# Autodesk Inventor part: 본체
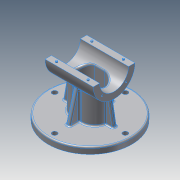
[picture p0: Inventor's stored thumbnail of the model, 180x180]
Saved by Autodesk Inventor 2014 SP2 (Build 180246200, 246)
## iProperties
Created: 2015-12
Part Number: 본체
Material: 알루미늄 6061
Document SubType Name: Modeling
Designer: mduedu
Density: 2.71 g/cm^3
Appearance: 알루미늄 - 평지
Mass: 616.11 g
Surface Area: 573.393 cm^2
Volume: 227.347 cm^3
Author: mduedu
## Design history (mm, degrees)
sketch "스케치1"
  geometry: C1 r 65 at (0, 0); 1 further point
  constraints: 1 centre point, 1 coincident
  dimensions: "d124" = 130 diameter of C1
extrude "돌출1" new body sketch "스케치1" distance "d3" = 10; taper "d4" = 0 deg
sketch "스케치2"
  geometry: C1 r 32.5 at (80, 0); 1 further point
  constraints: 1 centre point, 1 horizontal alignment
  dimensions: "d5" = 65 diameter of C1; "d125" = 80 distance of C1.centre point (0, 0)
extrude "돌출2" join sketch "스케치2" stored distance "d7" = 75; taper "d8" = 0 deg
sketch "스케치3"
  geometry: L1 (-27.5, -20)-(27.5, -20); L2 (27.5, -20)-(27.5, 20); L3 (27.5, 20)-(-27.5, 20); L4 (-27.5, 20)-(-27.5, -20); L5 (-27.5, -20)-(27.5, 20); L6 (27.5, -20)-(-27.5, 20); 1 further point
  constraints: 12 end point, 2 midpoint, 2 parallel, 1 horizontal, 1 perpendicular
  dimensions: "d9" = 55 distance of L2.end L3.end; "d11" = 40 distance of L1.end L2.end
extrude "돌출3" new body sketch "스케치3" stored distance "d12" = 75; taper "d13" = 0 deg
fillet "모깎기1"
fillet "모깎기2"
feature "결합1"
  node "솔리드2"
sketch "스케치4"
  geometry: L1 (-37.5, 47.5)-(37.5, 47.5) reference; L2 (32.5, 47.5)-(39.112, 10); L3 (37.5, 47.5)-(37.5, 112.5) reference; L4 (65, 10)-(-65, 10) reference; 1 further point
  constraints: 2 end point, 2 point on line
  dimensions: "d15" = 5 distance from line of L2.start L3; "d126" = 80 deg angle of L2 L1
sketch "스케치5"
  geometry: L1 (10, 35)-(56.569, 22.522); L2 (10, -65)-(10, 65) reference; L3 (10, 20)-(54.383, 20) reference; A1 r 32.5 centre (80, 0) between (56.569, 22.522) and (54.383, 20) reference; 1 further point
  constraints: 2 end point, 1 point on circle, 1 point on line
  dimensions: "d127" = 75 deg angle of L1 L2; "d128" = 15 distance of L1.start L3.start
feature "리브1" dims "d19" = 1, "d20" = 6, "d21" = 0, "d22" = 0, "d23" = 1, "d24" = 1
feature "리브2" dims "d25" = 1, "d26" = 6, "d27" = 0, "d28" = 0, "d29" = 1, "d30" = 1
fillet "모깎기4" dims "d31" = 2
fillet "모깎기5" dims "d32" = 2
fillet "모깎기6" dims "d33" = 2
fillet "모깎기7" dims "d41" = 2
hole "구멍2" diameter "d44" = 45; stored, may be unused: countersink angle "d48" = 90 deg, drill point angle "d50" = 118 deg; dims "d42" = 10, "d43" = 10, "d45" = 6, "d46" = 4, "d47" = 2, "d49" = 8
sketch "스케치7" dims "d52" = 26.5
  geometry: L1 (0, 0)-(32.5, 0); L2 (0, 0)-(22.981, 22.981); A1 r 32.5 centre (0, 0) between (32.5, 0) and (22.981, 22.981) reference; 3 further points
  constraints: 4 end point, 2 point on circle, 1 coincident, 1 horizontal, 1 point on line, 3 other
  dimensions: "d51" = 45 deg angle of L2 L1
hole "구멍3" sketch "스케치7" at (18.738, 18.738) diameter "d54" = 2.459; stored, may be unused: countersink angle "d58" = 90 deg, drill point angle "d60" = 118 deg; dims "d55" = 8, "d56" = 4, "d57" = 2, "d59" = 10
sketch "스케치9"
  geometry: L1 (-75, 82.5)-(75, 82.5); L2 (75, 82.5)-(75, 0); L3 (75, 0)-(-75, 0); L4 (-75, 0)-(-75, 82.5); C1 r 32.5 at (0, 0) reference; 2 further points
  constraints: 8 end point, 2 parallel, 1 coincident, 1 horizontal, 1 midpoint, 1 perpendicular
  dimensions: "d71" = 50 distance edge to line of C1 L1; "d116" = 150 distance between parallel lines of L2 L4
extrude "돌출5" cut sketch "스케치9" stored distance "d73" = 0; taper "d74" = 0 deg
node "작업 평면1"
sketch "스케치10"
  geometry: L1 (-7.5, 15)-(7.5, 15); L2 (-7.5, -15)-(7.5, -15); A1 r 20 centre (-7.5, 0) between (-7.5, 20) and (-26.977, 4.545) reference; A2 r 20 centre (7.5, 0) between (26.977, 4.545) and (7.5, 20) reference; A3 r 15 centre (-7.5, 0) between (-7.5, 15) and (-7.5, -15); A4 r 15 centre (7.5, 0) between (7.5, -15) and (7.5, 15); 1 further point
  constraints: 7 point on circle, 4 end point, 4 tangent, 3 point on line, 2 centre point, 2 coincident, 1 horizontal
  dimensions: "d77" = 5 radial gap between concentric circles of A3 A1
extrude "돌출6" cut sketch "스케치10" stored distance "d78" = 50; taper "d79" = 0 deg
fillet "모깎기10" dims "d80" = 3
sketch "스케치11"
  geometry: 2 further points
  constraints: 1 coincident
hole "구멍4" sketch "스케치11" at (0, 0) diameter "d81" = 12; stored, may be unused: countersink angle "d85" = 90 deg, drill point angle "d87" = 118 deg; dims "d82" = 8, "d83" = 40, "d84" = 10, "d86" = 10
sketch "스케치12"
  geometry: C1 r 10 at (0, 0); 1 further point
  constraints: 1 centre point, 1 coincident
  dimensions: "d88" = 20 diameter of C1
extrude "돌출7" cut sketch "스케치12" distance "d89" = 5; taper "d90" = 0 deg
chamfer "모따기1" distance "d91" = 1; stored, may be unused: second distance "d92" = 2, angle "d93" = 45 deg
fillet "모깎기11" dims "d94" = 0.5
fillet "모깎기12" dims "d115" = 0.3
sketch "스케치15"
  geometry: L1 (-75, 55)-(-75, 65) reference; L2 (0, 65)-(0, 55) reference; L3 (-75, 60)-(0, 60); C1 r 1.5 at (-62, 60); 1 further point
  constraints: 2 end point, 2 midpoint, 1 centre point, 1 point on line
  dimensions: "d117" = 3 diameter of C1; "d118" = 13 distance from line of C1.centre L1
extrude "돌출8" join sketch "스케치15" distance "d119" = 1.8; taper "d120" = 0 deg
chamfer "모따기2" distance "d121" = 0.5; stored, may be unused: second distance "d122" = 2, angle "d123" = 45 deg
sketch "스케치18" dims "d141" = 110
  geometry: C1 r 63 at (0, 0) reference; 2 further points
  constraints: 2 vertical alignment, 1 coincident, 2 other
hole "구멍8" sketch "스케치18" at (0, 55) diameter "d142" = 8; stored, may be unused: countersink angle "d146" = 90 deg, drill point angle "d148" = 118 deg; dims "d143" = 6, "d144" = 4, "d145" = 2, "d147" = 8
node "솔리드1"
mirror "대칭1"
mirror "대칭2"
pattern_circular "원형 패턴1" dims angle "d62" = 360 deg
mirror "대칭3"
mirror "대칭5"
mirror "대칭6"
pattern_circular "원형 패턴2" dims angle "d150" = 360 deg
mirror "대칭7"
